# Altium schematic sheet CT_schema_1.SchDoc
size 505 x 499 mm
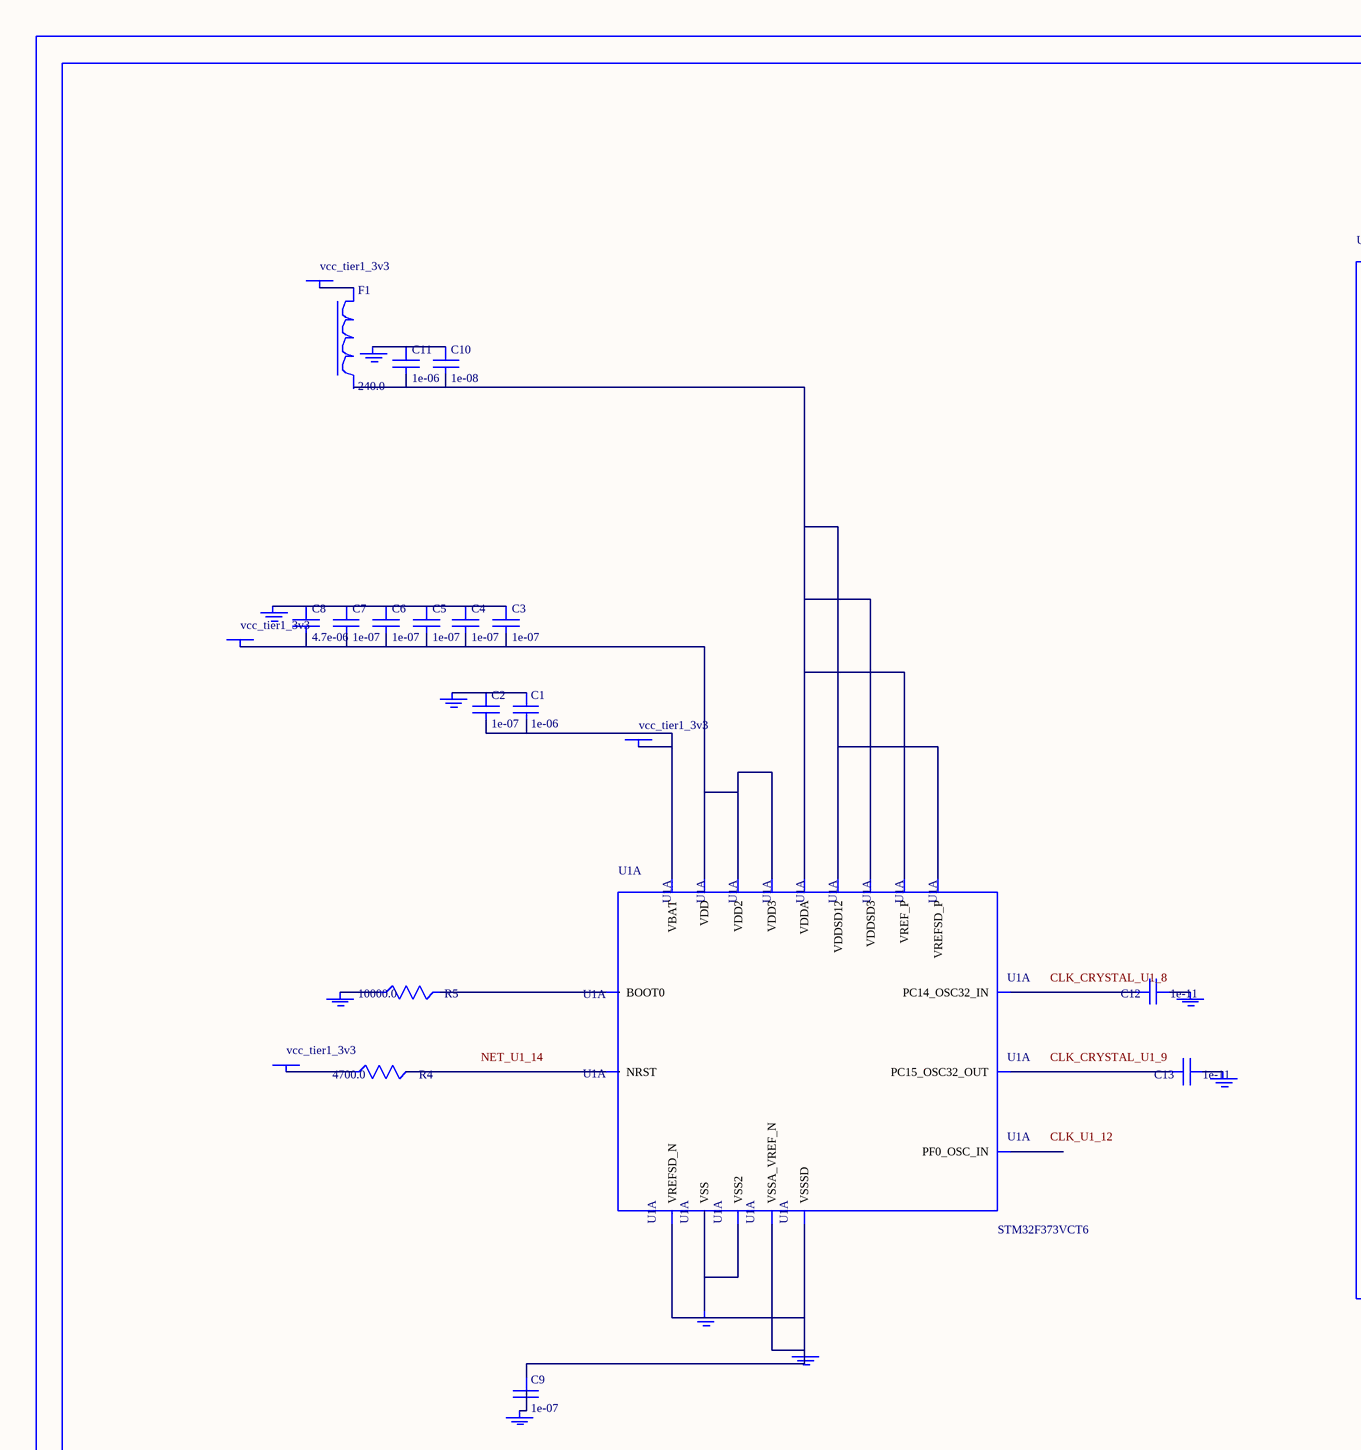
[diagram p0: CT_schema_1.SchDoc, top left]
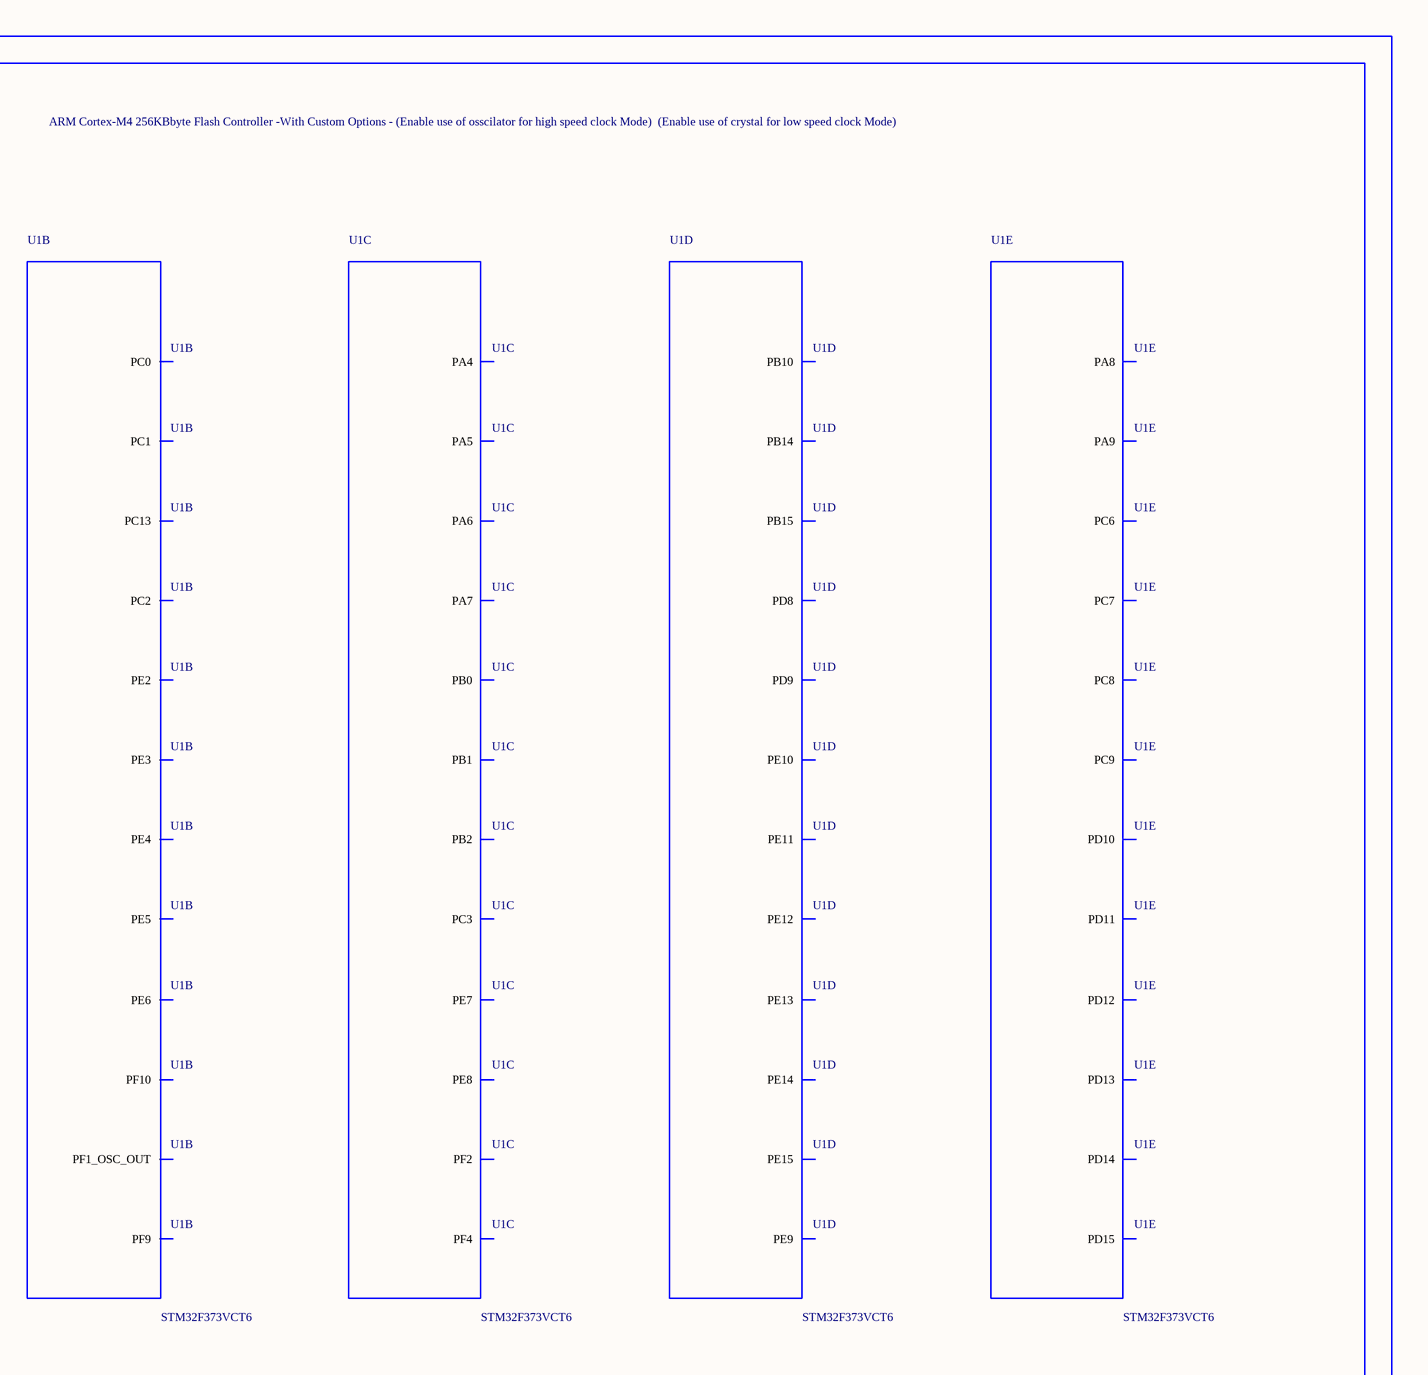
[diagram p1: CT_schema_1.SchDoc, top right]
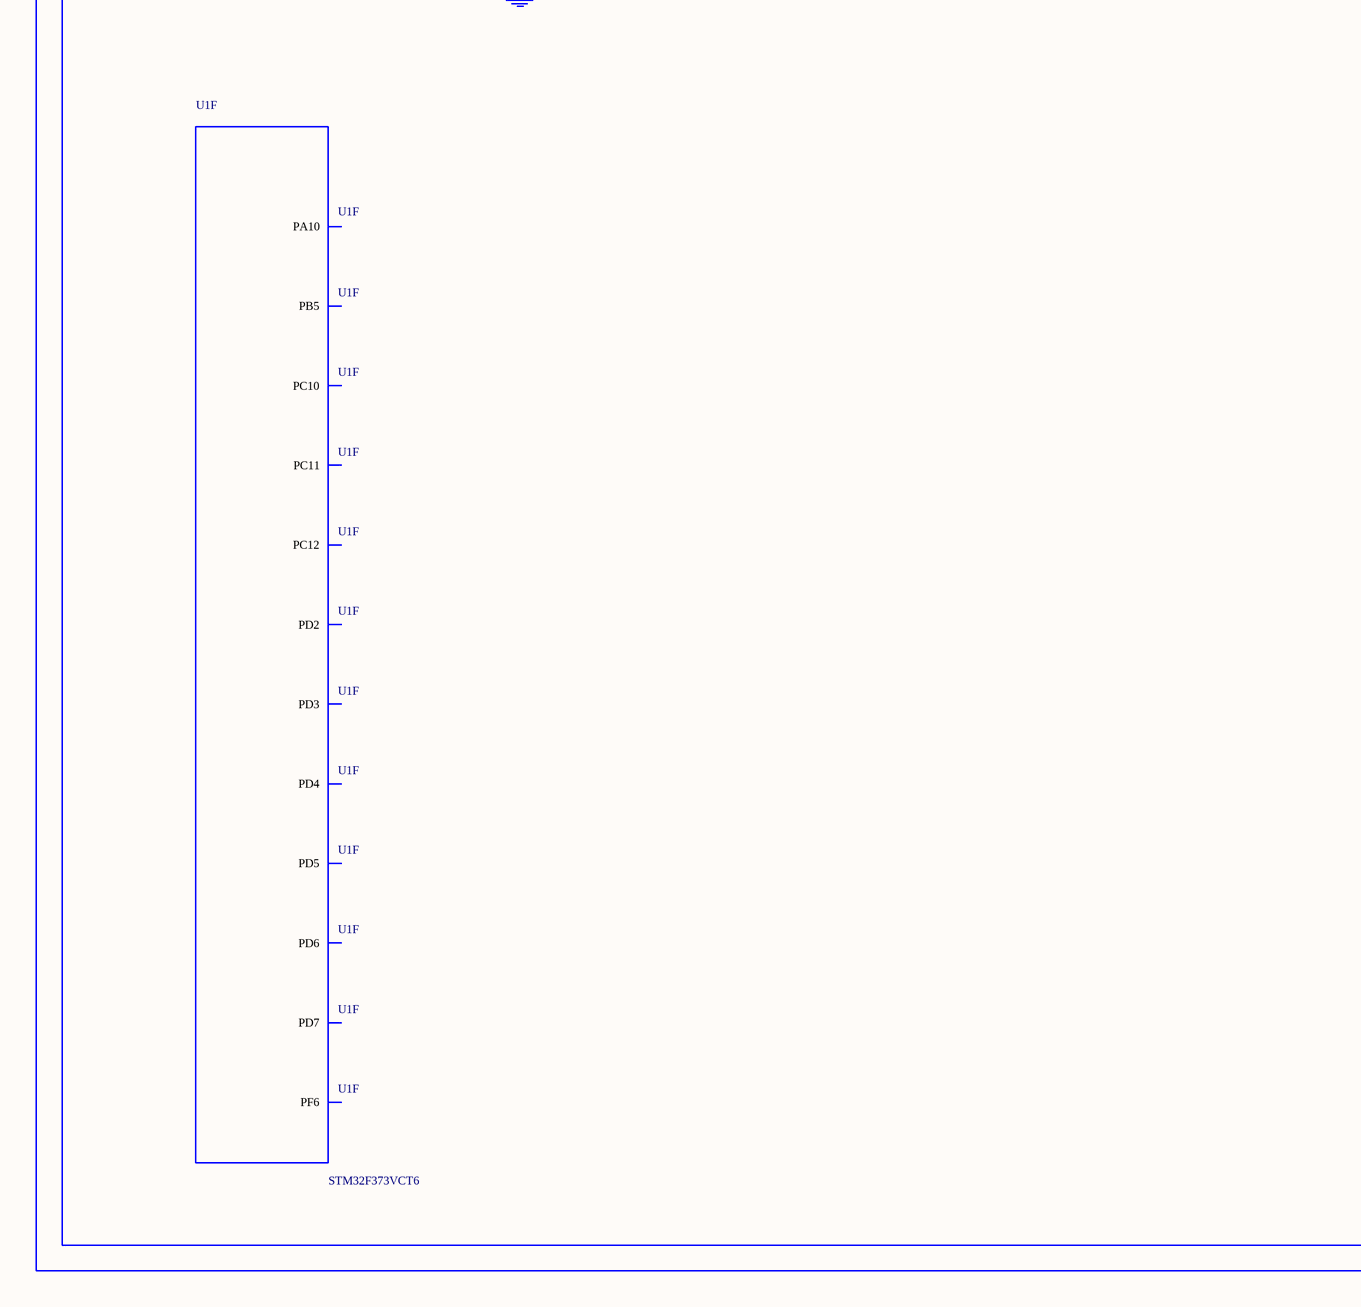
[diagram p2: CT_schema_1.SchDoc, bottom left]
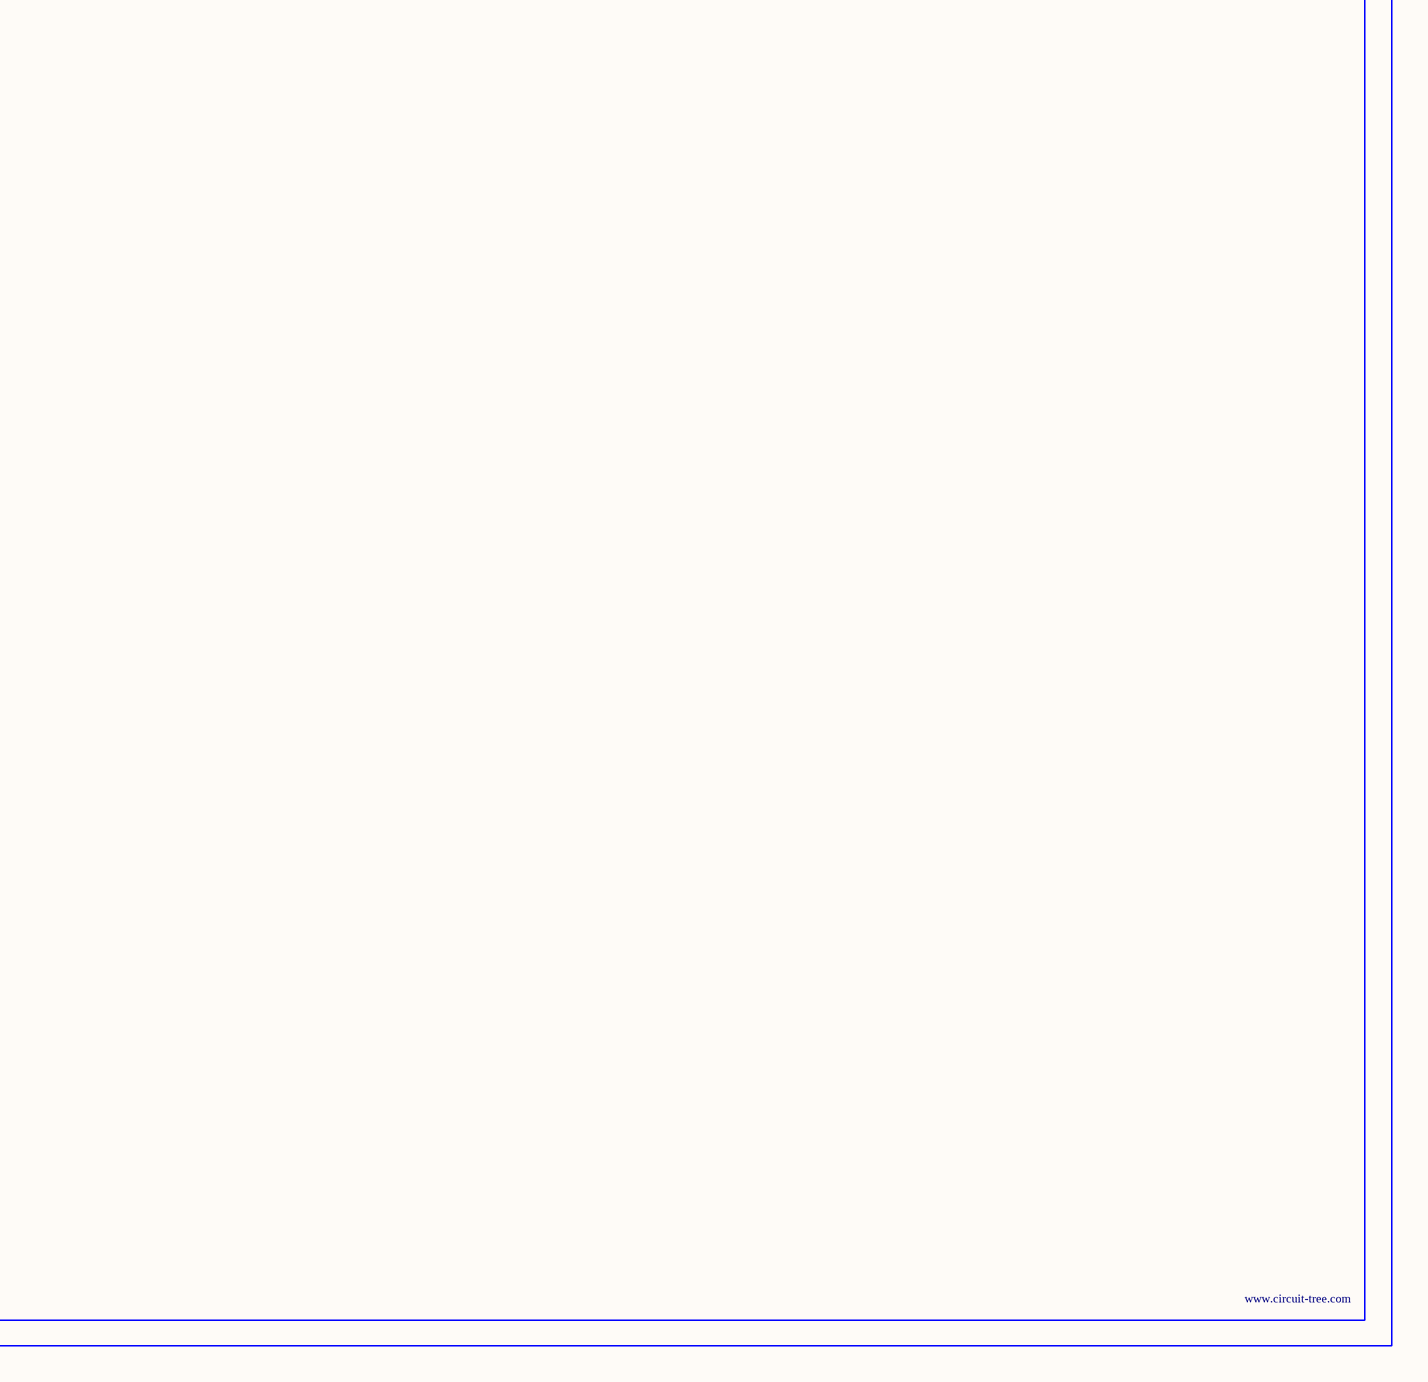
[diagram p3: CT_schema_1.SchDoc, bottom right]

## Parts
BORDER0  (no value)
C1  1e-06  [C0603]
C2  1e-07  [C0603]
C3  1e-07  [C0603]
C4  1e-07  [C0603]
C5  1e-07  [C0603]
C6  1e-07  [C0603]
C7  1e-07  [C0603]
C8  4.7e-06  [C0603]
C9  1e-07  [C0603]
C10  1e-08  [C0603]
C11  1e-06  [C0603]
C12  1e-11  [C0402]
C13  1e-11  [C0402]
F1  240.0  [L0603]
GND_INSTANCE_0_0  (no value)
GND_INSTANCE_0_1  (no value)
GND_INSTANCE_0_2  (no value)
GND_INSTANCE_0_3  (no value)
GND_INSTANCE_0_4  (no value)
GND_INSTANCE_0_5  (no value)
GND_INSTANCE_0_6  (no value)
GND_INSTANCE_0_7  (no value)
GND_INSTANCE_0_8  (no value)
POWER_INSTANCE_0_0  vcc_tier1_3v3
POWER_INSTANCE_0_1  vcc_tier1_3v3
POWER_INSTANCE_0_2  vcc_tier1_3v3
POWER_INSTANCE_0_3  vcc_tier1_3v3
R4  4700.0  [R0603]
R5  10000.0  [R0603]
U1  STM32F373VCT6  [LQFP100]  (parts A,B,C,D,E,F of 10)

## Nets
NetC1_1: C1.1 C2.1 GND_INSTANCE_0_0.0(GND)
NetC1_2: C1.2 C2.2 POWER_INSTANCE_0_0.0(PWR) U1.6(VBAT)
NetC3_1: C3.1 C4.1 C5.1 C6.1 C7.1 C8.1 GND_INSTANCE_0_5.0(GND)
NetC3_2: C3.2 C4.2 C5.2 C6.2 C7.2 C8.2 POWER_INSTANCE_0_2.0(PWR) U1.28(VDD) U1.75(VDD2) U1.100(VDD3)
NetC9_1: C9.1 GND_INSTANCE_0_3.0(GND) U1.20(VSSA_VREF_N) U1.48(VREFSD_N) U1.49(VSSSD)
NetC9_2: C9.2 GND_INSTANCE_0_6.0(GND)
NetC10_1: C10.1 C11.1 GND_INSTANCE_0_4.0(GND)
NetC10_2: C10.2 C11.2 U1.21(VDDA) U1.22(VREF_P) U1.50(VDDSD12) U1.51(VDDSD3) U1.52(VREFSD_P)
NetC12_1: C12.1 GND_INSTANCE_0_1.0(GND)
NetC12_2: C12.2 U1.8(PC14_OSC32_IN)
NetC13_1: C13.1 GND_INSTANCE_0_2.0(GND)
NetC13_2: C13.2 U1.9(PC15_OSC32_OUT)
NetF1_1: F1.1 POWER_INSTANCE_0_1.0(PWR)
NetGND_INSTANCE_0_7_0: GND_INSTANCE_0_7.0(GND) R5.1
NetGND_INSTANCE_0_8_0: GND_INSTANCE_0_8.0(GND) U1.74(VSS) U1.99(VSS2)
NetPOWER_INSTANCE_0_3_0: POWER_INSTANCE_0_3.0(PWR) R4.1
NetR4_2: R4.2 U1.14(NRST)
NetR5_2: R5.2 U1.94(BOOT0)

Not connected (* = marked no-connect by the designer): F1 2; U1 1(PE2) 2(PE3) 3(PE4) 4(PE5) 5(PE6) 7(PC13) 10(PF9) 11(PF10) 12(PF0_OSC_IN) 13(PF1_OSC_OUT) 15(PC0) 16(PC1) 17(PC2) 18(PC3) 19(PF2) 27(PF4) 29(PA4) 30(PA5) 31(PA6) 32(PA7) 35(PB0) 36(PB1) 37(PB2) 38(PE7) 39(PE8) 40(PE9) 41(PE10) 42(PE11) 43(PE12) 44(PE13) 45(PE14) 46(PE15) 47(PB10) 53(PB14) 54(PB15) 55(PD8) 56(PD9) 57(PD10) 58(PD11) 59(PD12) 60(PD13) 61(PD14) 62(PD15) 63(PC6) 64(PC7) 65(PC8) 66(PC9) 67(PA8) 68(PA9) 69(PA10) 73(PF6) 78(PC10) 79(PC11) 80(PC12) 83(PD2) 84(PD3) 85(PD4) 86(PD5) 87(PD6) 88(PD7) 91(PB5)

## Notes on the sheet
- Labels drawn without touching a wire or pin: CLK_CRYSTAL_U1_8, CLK_CRYSTAL_U1_9, CLK_U1_12, NET_U1_14

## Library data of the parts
BORDER0 = BORDER_PAGE0
C1 C11 = C0603C105K3RACTU
C2-C7 C9 = 06035C104K4Z2A
C8 = GRM188R6YA475KE15D
C10 = 06035C103K4Z2A
C12 C13 = C0402C100K3GACTU
F1 = Z0603C241ASMST
GND_INSTANCE_0_0-GND_INSTANCE_0_8 = GND
POWER_INSTANCE_0_0-POWER_INSTANCE_0_3 = PWR
R4 = RC0603JR-074K7L
R5 = RC0603JR-0710KL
